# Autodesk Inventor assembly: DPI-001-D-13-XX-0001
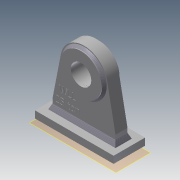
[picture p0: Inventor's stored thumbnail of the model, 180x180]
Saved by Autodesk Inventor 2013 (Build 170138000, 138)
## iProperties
Created: 2014-02
Part Number: DPI-001-D-13-XX-0001
Document SubType Name: Weldment
Designer: luiz.parente
Mass: 17967.3 g
Surface Area: 2679.27 cm^2
Volume: 2356.07 cm^3
Density: 7.626 g/cm^3
Project: DO TUGGER LINE
Description: OLHAL DE 25 TON PARA GUINCHO
Weld Material: Aluminum 6061, Welded
Author: luiz.parente
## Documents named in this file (4)
- C:\Users\LUIZ.PARENTE\Desktop\DPI-001-D-13-XX-0001\REV 01\INVENTOR\DPI-001-D-13-XX-0001.iam
- C:\Users\LUIZ.PARENTE\Desktop\DPI-001-D-13-XX-0001\REV 01\INVENTOR\DPI001D13XX0001_01.ipt
- C:\Users\LUIZ.PARENTE\Desktop\DPI-001-D-13-XX-0001\REV 01\INVENTOR\DPI001D13XX0001_02.ipt
- C:\Users\LUIZ.PARENTE\Desktop\DPI-001-D-13-XX-0001\REV 01\INVENTOR\DPI001D13XX0001_03.ipt
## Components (4 placed, 3 different names)
1. DPI001D13XX0001_01:1 — Flush:1, Mate:1, Flush:2, Mate:2
2. DPI001D13XX0001_02:1 — Flush:3, Mate:2, Flush:4, Mate:3, Mate:4, Mate:6, Mate:7
3. DPI001D13XX0001_03:1 — Mate:3, Mate:4, Mate:5
4. DPI001D13XX0001_03:2 — Mate:6, Mate:7, Mate:8
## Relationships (12: Mate 8, Flush 4)
- Flush:1: DPI001D13XX0001_01:1
- Mate:1: DPI001D13XX0001_01:1
- Flush:2: DPI001D13XX0001_01:1
- Flush:3: DPI001D13XX0001_02:1
- Mate:2: DPI001D13XX0001_01:1 ↔ DPI001D13XX0001_02:1
- Flush:4: DPI001D13XX0001_02:1
- Mate:3: DPI001D13XX0001_02:1 ↔ DPI001D13XX0001_03:1
- Mate:4: DPI001D13XX0001_02:1 ↔ DPI001D13XX0001_03:1
- Mate:5: DPI001D13XX0001_03:1
- Mate:6: DPI001D13XX0001_02:1 ↔ DPI001D13XX0001_03:2
- Mate:7: DPI001D13XX0001_02:1 ↔ DPI001D13XX0001_03:2
- Mate:8: DPI001D13XX0001_03:2
